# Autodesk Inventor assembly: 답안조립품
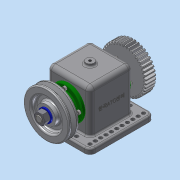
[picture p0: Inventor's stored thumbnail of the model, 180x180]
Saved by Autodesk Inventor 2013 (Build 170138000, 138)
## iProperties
Created: 2018-11
Part Number: 답안조립품
Document SubType Name: Assembly
Designer: dgall
Author: dgall
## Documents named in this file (13)
- C:\Users\dgall\Desktop\481107V1007\답안조립품.iam
- C:\Users\dgall\Desktop\481107V1007\본체.ipt
- C:\Users\dgall\Desktop\481107V1007\스퍼기어.ipt
- C:\Users\dgall\Desktop\481107V1007\축.ipt
- C:\Users\dgall\Desktop\481107V1007\커버.ipt
- C:\Users\dgall\Desktop\481107V1007\볼트 M4.ipt
- C:\Users\dgall\Desktop\481107V1007\베어링 6203.ipt
- C:\Users\dgall\Desktop\481107V1007\부시.ipt
- C:\Users\dgall\Desktop\481107V1007\키 5x5x12.ipt
- C:\Users\dgall\Desktop\481107V1007\V벨트풀리.ipt
- C:\Users\dgall\Desktop\481107V1007\너트 M12x1.25.ipt
- C:\Users\dgall\Desktop\481107V1007\오일 실 26 38 8.ipt
- C:\Users\dgall\Desktop\481107V1007\와셔 12x24.ipt
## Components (1 placed, 1 different names)
1. V벨트풀리:1
